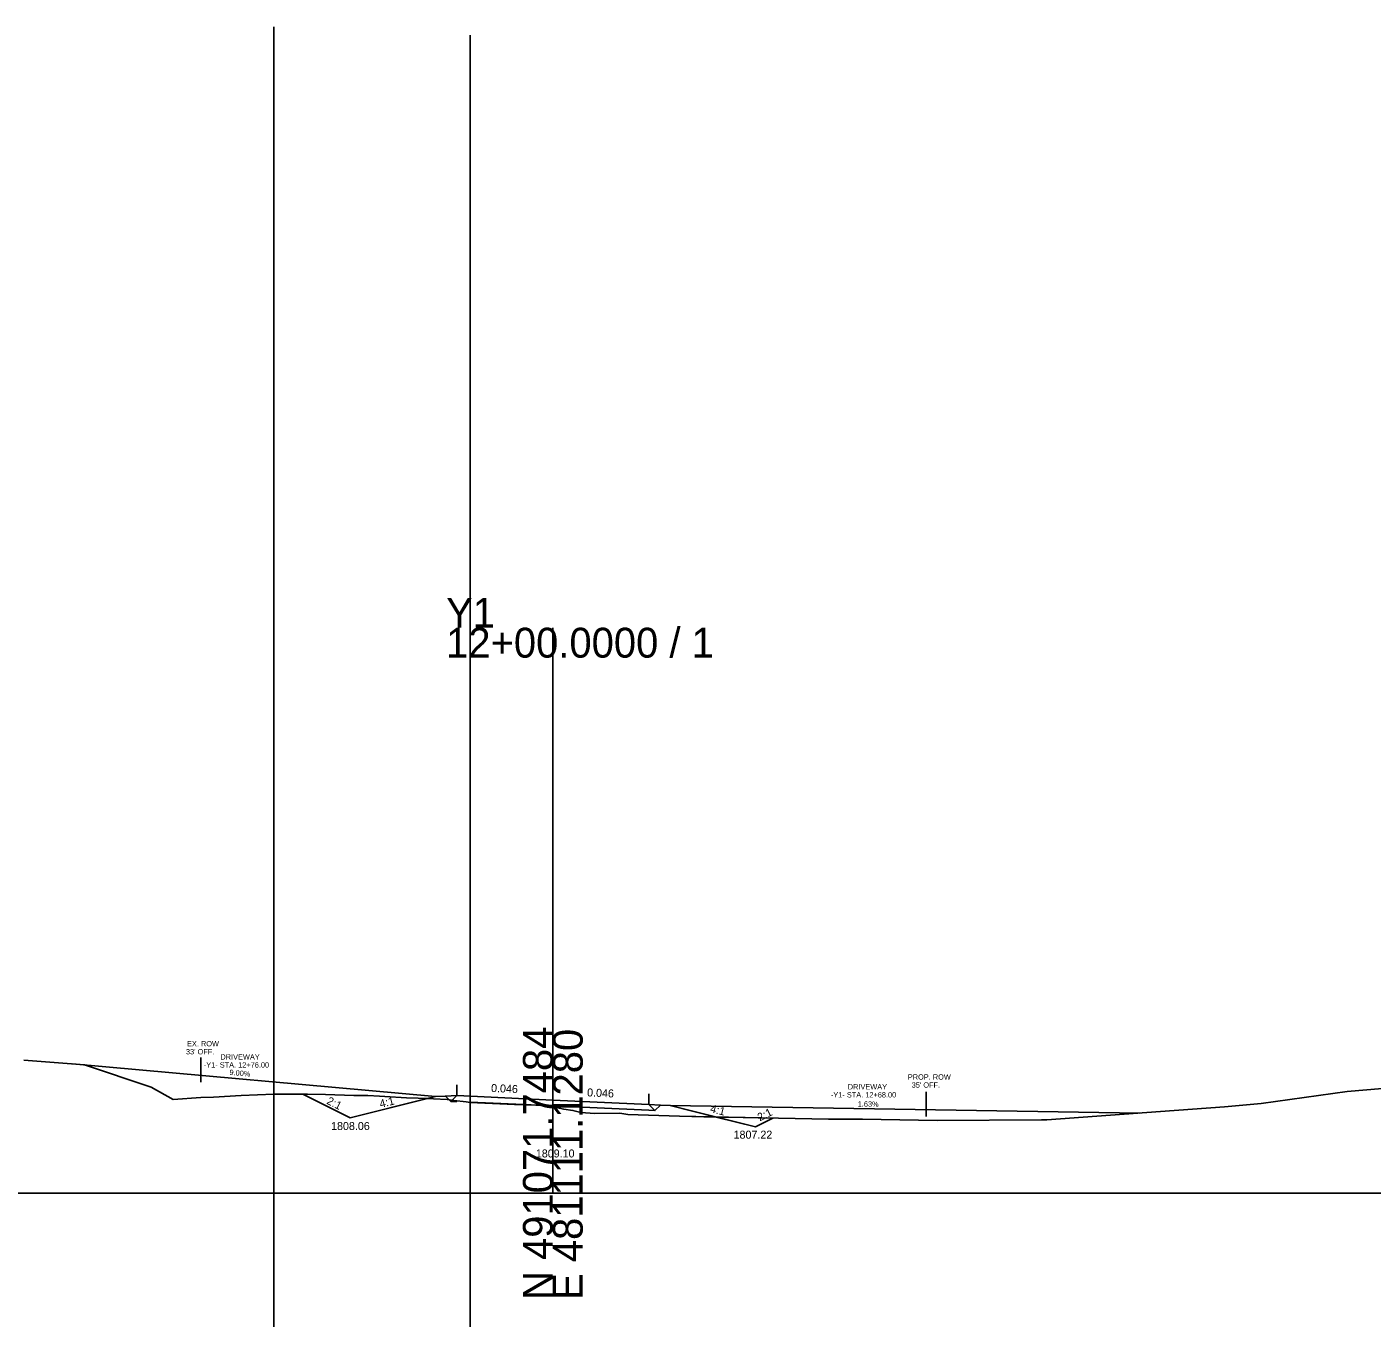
# Model space of a CAD drawing. Extents: x -26 to 403, y -10 to 6561.
# Drawn here: x 150.7 to 276.8, y 1988.3 to 2109.3 of the extents above; entities that cross this region are included whole.
import ezdxf

# ---------------------------------------------------------------- set-up
doc = ezdxf.new("R2010")
doc.units = 0
for name, color, linetype in [('Exist Cross Section Cell', 7, 'Continuous'), ('Exist XS Center Line Elevation Label', 7, 'Continuous'), ('Exist XS Ground Line', 7, 'Continuous'), ('Prop Road Sect_ Boring - Header (ID Tx)', 7, 'Continuous'), ('Prop Road Sect_ Boring - Material (Outline)', 7, 'Continuous'), ('Prop Road Sect_ Material - Tx (Composite Desc)', 7, 'Continuous'), ('Prop XS Ditch Slope Text', 7, 'Continuous'), ('Prop XS Ditch Standard Text', 7, 'Continuous'), ('Prop XS EOT Tick Mark', 7, 'Continuous'), ('Prop XS Finish Grade', 7, 'Continuous'), ('Prop XS Finish Grade Earthwork', 7, 'Continuous'), ('Prop XS Finish Grade Pavement', 7, 'Continuous'), ('Prop XS Pvmt Edge Slope', 7, 'Continuous'), ('Prop XS SE Text', 7, 'Continuous'), ('Prop XS Side Slope Text', 7, 'Continuous'), ('Prop XS Subgrade Earthwork', 7, 'Continuous'), ('Scratch_Level_1', 7, 'Continuous')]:
    doc.layers.add(name, color=color, linetype=linetype)

msp = doc.modelspace()

# ---------------------------------------------------------------- linework, layer by layer
at = {"layer": 'Exist Cross Section Cell'}
for p, q in [((200, 2000), (200, 2052.98)), ((0, 2000), (200, 2000)), ((200, 2000), (400, 2000))]:
    msp.add_line(p, q, dxfattribs=at)
at = {"layer": 'Exist XS Ground Line'}
msp.add_lwpolyline([(150.43, 2012.47), (156.11, 2012.04), (162.35, 2009.92), (164.42, 2008.79), (167.02, 2008.96), (168.19, 2009.01), (170.79, 2009.14), (173.85, 2009.27), (175.05, 2009.28), (176.15, 2009.28), (177.02, 2009.27), (178.69, 2009.24), (181.34, 2009.17), (181.73, 2009.16), (182.65, 2009.14), (183.76, 2009.09), (184.26, 2009.06), (186.29, 2008.95), (187.37, 2008.91), (188.82, 2008.84), (190.1, 2008.77), (190.73, 2008.69), (191.89, 2008.55), (192.26, 2008.51), (196.42, 2008.31), (199.55, 2008.21), (200, 2008.1), (201.03, 2007.86), (201.88, 2007.75), (202.64, 2007.57), (203.95, 2007.47), (206.27, 2007.51), (207.04, 2007.37), (211.88, 2007.23), (216.45, 2007.11), (225.85, 2006.93), (229.02, 2006.95), (236.02, 2006.8), (245.79, 2006.87), (246.3, 2006.88), (256.94, 2007.64), (262.95, 2008.08), (266.39, 2008.42), (274.44, 2009.53), (277.74, 2009.82)], dxfattribs=at)
at = {"layer": 'Prop Road Sect_ Boring - Header (ID Tx)'}
for points in [[(191, 2009.14), (189.94, 2009.1), (190.45, 2008.59)], [(209, 2008.31), (210.09, 2008.26), (209.57, 2007.74)]]:
    msp.add_lwpolyline(points, close=True, dxfattribs=at)
at = {"layer": 'Prop Road Sect_ Boring - Material (Outline)'}
for p, q in [((189, 2009.06), (155, 2012.12)), ((167, 2012.73), (167, 2010.41)), ((235, 2009.51), (235, 2007.2)), ((211, 2008.22), (255, 2007.5))]:
    msp.add_line(p, q, dxfattribs=at)
at = {"layer": 'Prop Road Sect_ Material - Tx (Composite Desc)'}
for points in [[(181, 2007.06), (176.56, 2009.28), (177.02, 2009.27), (178.69, 2009.24), (181.34, 2009.17), (181.73, 2009.16), (182.65, 2009.14), (183.76, 2009.09), (184.26, 2009.06), (186.29, 2008.95), (187.37, 2008.91), (188.23, 2008.87)], [(189, 2009.06), (189.94, 2009.1), (190.3, 2008.75), (190.1, 2008.77), (188.82, 2008.84), (188.23, 2008.87)], [(191, 2008.6), (191, 2008.66), (190.73, 2008.69), (190.3, 2008.75), (190.45, 2008.59)], [(199.41, 2008.21), (192.26, 2008.54), (192.26, 2008.51), (196.42, 2008.31)], [(209, 2007.77), (200, 2008.18), (199.55, 2008.21), (200, 2008.1), (201.03, 2007.86), (201.88, 2007.75), (202.64, 2007.57), (203.95, 2007.47), (206.27, 2007.51), (207.04, 2007.37), (211.88, 2007.23), (215.3, 2007.14), (211, 2008.22), (210.09, 2008.26), (209.57, 2007.74)], [(219, 2006.22), (220.62, 2007.03), (216.45, 2007.11), (215.3, 2007.14)]]:
    msp.add_lwpolyline(points, close=True, dxfattribs=at)
at = {"layer": 'Prop XS EOT Tick Mark'}
for p, q in [((191, 2009.14), (191, 2010.14)), ((209, 2008.31), (209, 2009.31))]:
    msp.add_line(p, q, dxfattribs=at)
at = {"layer": 'Prop XS Finish Grade'}
for p, q in [((191, 2009.14), (189.94, 2009.1)), ((209, 2008.31), (210.09, 2008.26))]:
    msp.add_line(p, q, dxfattribs=at)
at = {"layer": 'Prop XS Finish Grade Earthwork'}
for p, q in [((181, 2007.06), (176.56, 2009.28)), ((189, 2009.06), (181, 2007.06)), ((189, 2009.06), (189.94, 2009.1)), ((210.09, 2008.26), (211, 2008.22)), ((211, 2008.22), (219, 2006.22)), ((219, 2006.22), (220.62, 2007.03))]:
    msp.add_line(p, q, dxfattribs=at)
at = {"layer": 'Prop XS Finish Grade Pavement'}
for p, q in [((191, 2009.14), (200, 2008.72)), ((200, 2008.72), (209, 2008.31))]:
    msp.add_line(p, q, dxfattribs=at)
at = {"layer": 'Prop XS Pvmt Edge Slope'}
for p, q in [((191, 2009.14), (190.45, 2008.59)), ((209, 2008.31), (209.57, 2007.74))]:
    msp.add_line(p, q, dxfattribs=at)
at = {"layer": 'Prop XS Subgrade Earthwork'}
for p, q in [((190.45, 2008.59), (189.94, 2009.1)), ((191, 2008.6), (190.45, 2008.59)), ((191, 2008.6), (191, 2008.66)), ((200, 2008.18), (192.26, 2008.54)), ((192.26, 2008.54), (192.26, 2008.51)), ((209, 2007.77), (200, 2008.18)), ((209.57, 2007.74), (210.09, 2008.26)), ((209, 2007.77), (209.57, 2007.74))]:
    msp.add_line(p, q, dxfattribs=at)
at = {"layer": 'Scratch_Level_1'}
for p, q in [((173.85, 2109.27), (173.85, 1909.27)), ((192.26, 2108.51), (192.26, 1908.51))]:
    msp.add_line(p, q, dxfattribs=at)

# ---------------------------------------------------------------- texts
at = {"layer": 'Exist Cross Section Cell'}
for s, p in [('Y1', (190, 2052.98)), ('12+00.0000 / 1', (190, 2050.18))]:
    msp.add_text(s, height=2.8, dxfattribs=at).set_placement(p)
for s, p in [('N 491071.7484', (200, 1990)), ('E 481111.1280', (202.8, 1990))]:
    msp.add_text(s, height=2.8, rotation=90, dxfattribs=at).set_placement(p)
at = {"layer": 'Exist XS Center Line Elevation Label'}
msp.add_text('1809.10', height=0.75, dxfattribs=at).set_placement((198.41, 2003.35))
at = {"layer": 'Prop Road Sect_ Boring - Material (Outline)'}
for s, p in [("33' OFF.", (165.62, 2013.01)), ('EX. ROW', (165.72, 2013.76)), ('-Y1- STA. 12+76.00', (167.29, 2011.77)), ('DRIVEWAY', (168.85, 2012.52)), ('PROP. ROW', (233.27, 2010.64)), ('-Y1- STA. 12+68.00', (226.06, 2008.97)), ('DRIVEWAY', (227.64, 2009.72)), ("35' OFF.", (233.63, 2009.89))]:
    msp.add_text(s, height=0.5, dxfattribs=at).set_placement(p)
for s, rotation, p in [('9.00%', 354.8543, (169.68, 2011.09)), ('1.63%', 358.9917, (228.57, 2008.12))]:
    msp.add_text(s, height=0.5, rotation=rotation, dxfattribs=at).set_placement(p)
at = {"layer": 'Prop XS Ditch Slope Text'}
for rotation, p in [(14.0362, (183.86, 2007.99)), (345.9638, (214.7, 2007.6))]:
    msp.add_text('4:1', height=0.75, rotation=rotation, dxfattribs=at).set_placement(p)
at = {"layer": 'Prop XS Ditch Standard Text'}
for s, p in [('1808.06', (179.22, 2005.92)), ('1807.22', (216.94, 2005.11))]:
    msp.add_text(s, height=0.75, dxfattribs=at).set_placement(p)
at = {"layer": 'Prop XS SE Text'}
for p in [(194.2, 2009.49), (203.2, 2009.08)]:
    msp.add_text('0.046', height=0.75, rotation=357.3617, dxfattribs=at).set_placement(p)
at = {"layer": 'Prop XS Side Slope Text'}
for rotation, p in [(333.4349, (178.74, 2008.41)), (26.5651, (219.4, 2006.72))]:
    msp.add_text('2:1', height=0.75, rotation=rotation, dxfattribs=at).set_placement(p)

doc.saveas('drawing.dxf')
